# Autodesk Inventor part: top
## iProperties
Author: Administrator
Created: 2001-03
Part Number: top
Document SubType Name: Modeling
Designer: Administrator
Control State: 0
Master: False
Checked Out: False
PropertySet Name: Design Tracking Control
Shininess: 20.0
PropertySet Name: _Private Model Information
Density: 0.0
Volumn: 0.0
Area: 0.0
PropertySet Name: Model Information
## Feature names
1. Extrusion1
